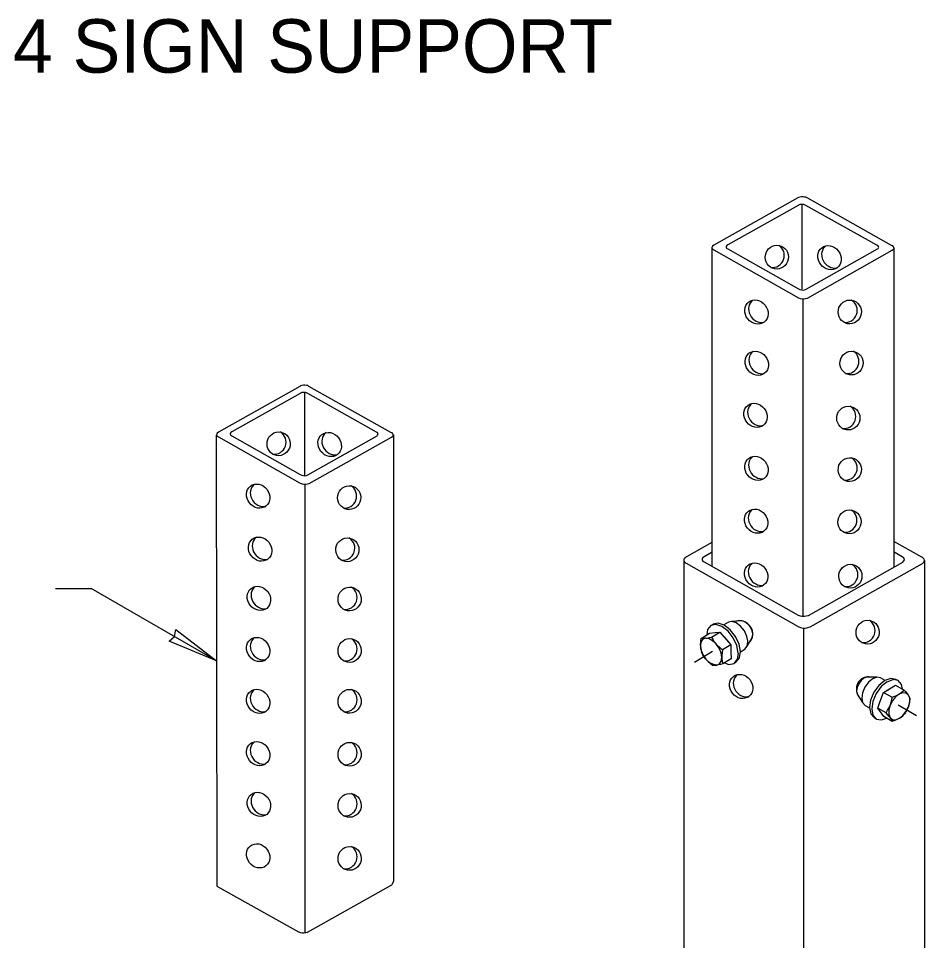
# Model space of a CAD drawing. Extents: x 99862 to 103680, y 99470 to 102076.
# Drawn here: x 101983.5 to 102390.3, y 100461.4 to 100875.6 of the extents above; entities that cross this region are included whole.
import ezdxf

# ---------------------------------------------------------------- set-up
doc = ezdxf.new("R2010")
doc.units = 0
for name, color, linetype in [('Level 15', 7, 'Continuous'), ('Level 20', 7, 'Continuous'), ('Level 3', 7, 'Continuous'), ('Level 5', 7, 'Continuous'), ('Level 9', 7, 'Continuous')]:
    doc.layers.add(name, color=color, linetype=linetype)

msp = doc.modelspace()

# ---------------------------------------------------------------- linework, layer by layer
at = {"layer": 'Level 15'}
for p, q in [((102000.1, 100619.57), (102016.1, 100619.57)), ((102072.39, 100587.07), (102016.1, 100619.57)), ((102286.95, 100586.46), (102295.04, 100591.39)), ((102386.64, 100562.41), (102378.4, 100567.09))]:
    msp.add_line(p, q, dxfattribs=at)
msp.add_lwpolyline([(102072.39, 100587.07), (102051.13, 100595.9), (102053.53, 100597.96), (102054.11, 100601.07)], close=True, dxfattribs=at)
at = {"layer": 'Level 3'}
for p, q in [((102335.18, 100792.03), (102335.18, 100754.01)), ((102335.82, 100607.07), (102335.82, 100749.87)), ((102112.05, 100670.24), (102112.05, 100707.51)), ((102072.26, 100688.3), (102072.51, 100485.85)), ((102151.85, 100688.51), (102151.85, 100488.15)), ((102112.05, 100666.45), (102112.05, 100465.01)), ((102292.9, 100601.14), (102292.51, 100598.72)), ((102336.03, 100354.46), (102336.03, 100601.71)), ((102304.75, 100585.94), (102306.21, 100587.74)), ((102306.67, 100590.55), (102306.21, 100587.74)), ((102373.51, 100577.68), (102376.19, 100578.64)), ((102378.46, 100578.23), (102376.19, 100578.64)), ((102370.91, 100560.5), (102373.21, 100561.33)), ((102151.85, 100488.15), (102151.16, 100486.47)), ((102072.51, 100485.85), (102109.31, 100465.35))]:
    msp.add_line(p, q, dxfattribs=at)
for points in [[(102376.5, 100772.58), (102376.44, 100772.7), (102376.36, 100773.02), (102376.08, 100773.43), (102375.51, 100773.57), (102337.6, 100794.94), (102337.03, 100795.36), (102336.46, 100795.36), (102335.75, 100795.5), (102335.04, 100795.5), (102334.33, 100795.36), (102333.76, 100795.22), (102333.34, 100794.94), (102295.71, 100773.71), (102295.14, 100773.3), (102294.87, 100772.78), (102294.84, 100772.71)], [(102333.62, 100754.15), (102334.33, 100753.87), (102335.04, 100753.73), (102335.75, 100753.59), (102336.46, 100753.73), (102337.17, 100754.01), (102369.12, 100772.05), (102369.4, 100772.32), (102369.69, 100772.88), (102369.55, 100773.16), (102369.26, 100773.57), (102368.84, 100773.71), (102337.03, 100791.61), (102336.46, 100791.89), (102336.03, 100792.03), (102335.47, 100792.03), (102334.9, 100792.03), (102334.33, 100792.03), (102333.76, 100791.75), (102333.48, 100791.61), (102301.96, 100773.85), (102301.53, 100773.57), (102301.25, 100773.16), (102301.25, 100772.88), (102301.39, 100772.46), (102301.53, 100772.32), (102301.96, 100772.05), (102333.62, 100754.15)], [(102294.86, 100772.74), (102294.86, 100640.13)], [(102294.86, 100772.46), (102295, 100772.19), (102295.28, 100771.91), (102295.71, 100771.63), (102333.62, 100750.12), (102334.47, 100749.85), (102335.32, 100749.71), (102336.03, 100749.71), (102336.89, 100749.85), (102337.74, 100749.99), (102375.79, 100771.49), (102376.36, 100771.91), (102376.43, 100772.19)], [(102376.5, 100772.58), (102376.5, 100640.71)], [(102151.67, 100688.53), (102151.53, 100689.07), (102151.25, 100689.47), (102150.7, 100689.61), (102113.91, 100710.34), (102113.36, 100710.75), (102112.81, 100710.75), (102112.12, 100710.88), (102111.43, 100710.88), (102110.75, 100710.75), (102110.19, 100710.61), (102109.78, 100710.34), (102073.27, 100689.74), (102072.72, 100689.34), (102072.58, 100688.94), (102072.26, 100688.3)], [(102110.06, 100670.76), (102110.75, 100670.49), (102111.43, 100670.36), (102112.12, 100670.22), (102112.81, 100670.36), (102113.5, 100670.63), (102144.5, 100688.13), (102144.78, 100688.4), (102145.05, 100688.94), (102144.91, 100689.2), (102144.64, 100689.61), (102144.23, 100689.74), (102113.36, 100707.11), (102112.81, 100707.38), (102112.4, 100707.51), (102111.85, 100707.51), (102111.3, 100707.51), (102110.75, 100707.51), (102110.19, 100707.24), (102109.92, 100707.11), (102079.33, 100689.88), (102078.92, 100689.61), (102078.64, 100689.2), (102078.64, 100688.94), (102078.78, 100688.53), (102078.92, 100688.4), (102079.33, 100688.13), (102110.06, 100670.76)], [(102072.58, 100688.26), (102072.86, 100687.99), (102073.27, 100687.72), (102110.06, 100666.86)], [(102110.06, 100666.86), (102110.88, 100666.59), (102111.71, 100666.45), (102112.4, 100666.45), (102113.23, 100666.59), (102114.05, 100666.72), (102150.98, 100687.59), (102151.53, 100687.99), (102151.6, 100688.26)], [(102376.5, 100640.71), (102376.5, 100629)], [(102390.27, 100632.16), (102390.28, 100632.19), (102390.13, 100632.74), (102389.57, 100633.3), (102389, 100633.58), (102376.5, 100640.65)], [(102294.86, 100640.24), (102283.35, 100633.71), (102282.64, 100633.16), (102282.22, 100632.74), (102282.22, 100632.3)], [(102294.86, 100640.13), (102294.86, 100629.41)], [(102282.22, 100632.52), (102282.22, 100384.98), (102282.33, 100384.6)], [(102295, 100635.93), (102291.31, 100633.85), (102290.74, 100633.44), (102290.45, 100633.02), (102290.45, 100632.47), (102290.6, 100632.05), (102290.88, 100631.77), (102291.31, 100631.49), (102333.48, 100607.63), (102334.47, 100607.21), (102335.32, 100607.07), (102336.32, 100607.07), (102337.17, 100607.21), (102338.16, 100607.49), (102380.48, 100631.36), (102381.05, 100631.91), (102381.33, 100632.47), (102381.19, 100633.02), (102380.76, 100633.44), (102380.2, 100633.71), (102376.65, 100635.8)], [(102282.22, 100632.3), (102282.22, 100632.19), (102282.36, 100631.63), (102282.79, 100631.22), (102283.21, 100630.94), (102333.48, 100602.5), (102334.61, 100602.08), (102335.61, 100601.8), (102336.74, 100601.8), (102337.88, 100602.08), (102338.87, 100602.36), (102389.42, 100630.8), (102389.99, 100631.36), (102390.27, 100632.16)], [(102390.28, 100632.16), (102390.28, 100385.26), (102390.24, 100385.2)], [(102296.63, 100603.43), (102294.37, 100602.93), (102294.37, 100602.93)], [(102299.33, 100602.56), (102296.63, 100603.43), (102296.63, 100603.43)], [(102294.37, 100602.93), (102292.9, 100601.14), (102292.9, 100601.14)], [(102302.07, 100600.46), (102299.33, 100602.56), (102299.33, 100602.56)], [(102304.43, 100597.43), (102302.07, 100600.46), (102302.07, 100600.46)], [(102306.04, 100593.95), (102304.43, 100597.43), (102304.43, 100597.43)], [(102306.67, 100590.55), (102306.67, 100590.55), (102306.04, 100593.95), (102306.04, 100593.95)], [(102300.4, 100586.12), (102302.49, 100585.44), (102302.49, 100585.44)], [(102302.49, 100585.44), (102304.75, 100585.94), (102304.75, 100585.94)], [(102370.83, 100575.48), (102368.57, 100572.38), (102368.57, 100572.38)], [(102373.51, 100577.68), (102373.51, 100577.68), (102370.83, 100575.48), (102370.83, 100575.48)], [(102379.99, 100576.49), (102378.46, 100578.23), (102378.46, 100578.23)], [(102380.42, 100574.34), (102379.99, 100576.49), (102379.99, 100576.49)], [(102368.57, 100572.38), (102367.07, 100568.85), (102367.07, 100568.85)], [(102367.07, 100568.85), (102366.55, 100565.44), (102366.55, 100565.44)], [(102366.55, 100565.44), (102367.1, 100562.65), (102367.1, 100562.65)], [(102367.1, 100562.65), (102368.63, 100560.92), (102368.63, 100560.92)], [(102368.63, 100560.92), (102370.91, 100560.5), (102370.91, 100560.5)], [(102109.31, 100465.35), (102110.14, 100465.08), (102110.96, 100464.95), (102111.65, 100464.95), (102112.48, 100465.08), (102113.31, 100465.22), (102151.16, 100486.47)]]:
    msp.add_lwpolyline(points, dxfattribs=at)
for centre, major_axis, ratio in [((102323.97, 100768.38), (-0.95, -5.27), 0.972281), ((102347.62, 100768.13), (-3.5, 4.49), 0.875232), ((102314.82, 100743.71), (-3.5, 4.49), 0.875232), ((102356.7, 100743.76), (-0.95, -5.27), 0.972281), ((102314.97, 100720.68), (-3.5, 4.49), 0.875232), ((102357.48, 100720.79), (-0.95, -5.27), 0.972281), ((102314.4, 100697.3), (-3.5, 4.49), 0.875232), ((102356.06, 100696.09), (-0.95, -5.27), 0.972281), ((102100.32, 100684.56), (-0.95, -5.27), 0.972281), ((102123.24, 100684.21), (-3.5, 4.49), 0.875232), ((102314.82, 100673.5), (-3.5, 4.49), 0.875232), ((102356.7, 100672.92), (-0.95, -5.27), 0.972281), ((102091.14, 100661.04), (-3.5, 4.49), 0.875232), ((102131.98, 100660.36), (-0.95, -5.27), 0.972281), ((102314.68, 100649.77), (-3.5, 4.49), 0.875232), ((102356.56, 100649.48), (-0.95, -5.27), 0.972281), ((102092, 100637.24), (-3.5, 4.49), 0.875232), ((102131.17, 100636.95), (-0.95, -5.27), 0.972281), ((102314.68, 100625.63), (-3.5, 4.49), 0.875232), ((102356.98, 100625.06), (-0.95, -5.27), 0.972281), ((102091.48, 100615.12), (-3.5, 4.49), 0.875232), ((102132.19, 100614.83), (-0.95, -5.27), 0.972281), ((102364.72, 100599.94), (-0.95, -5.27), 0.972281), ((102091.14, 100592.16), (-3.5, 4.49), 0.875232), ((102132.19, 100591.7), (-0.95, -5.27), 0.972281), ((102307.96, 100575.56), (-3.5, 4.49), 0.875232), ((102091.14, 100568.86), (-3.5, 4.49), 0.875232), ((102132.19, 100568.91), (-0.95, -5.27), 0.972281), ((102091.14, 100545.39), (-3.5, 4.49), 0.875232), ((102132.19, 100545.11), (-0.95, -5.27), 0.972281), ((102091.48, 100522.6), (-3.5, 4.49), 0.875232), ((102132.19, 100522.14), (-0.95, -5.27), 0.972281), ((102091.14, 100499.47), (-3.5, 4.49), 0.875232), ((102132.19, 100498.34), (-0.95, -5.27), 0.972281)]:
    msp.add_ellipse(centre, major_axis=major_axis, ratio=ratio, dxfattribs=at)
for centre, major_axis, ratio, start_param, end_param in [((102322.12, 100769.06), (-0.95, -5.27), 0.972281, 0.021287, 2.783374), ((102349.35, 100768.87), (-3.5, 4.49), 0.875232, 6.248227, 9.013354), ((102316.55, 100744.45), (-3.5, 4.49), 0.875232, 6.248227, 9.013354), ((102354.85, 100744.43), (-0.95, -5.27), 0.972281, 0.021287, 2.783374), ((102316.69, 100721.42), (-3.5, 4.49), 0.875232, 6.248227, 9.013354), ((102355.63, 100721.47), (-0.95, -5.27), 0.972281, 0.021287, 2.783374), ((102316.12, 100698.04), (-3.5, 4.49), 0.875232, 6.248227, 9.013354), ((102354.21, 100696.77), (-0.95, -5.27), 0.972281, 0.021287, 2.783374), ((102098.48, 100685.24), (-0.95, -5.27), 0.972281, 0.021287, 2.783374), ((102124.97, 100684.96), (-3.5, 4.49), 0.875232, 6.248227, 9.013354), ((102316.55, 100674.25), (-3.5, 4.49), 0.875232, 6.248227, 9.013354), ((102354.85, 100673.6), (-0.95, -5.27), 0.972281, 0.021287, 2.783374), ((102092.87, 100661.79), (-3.5, 4.49), 0.875232, 6.248227, 9.013354), ((102130.13, 100661.04), (-0.95, -5.27), 0.972281, 0.021287, 2.783374), ((102316.41, 100650.52), (-3.5, 4.49), 0.875232, 6.248227, 9.013354), ((102354.71, 100650.15), (-0.95, -5.27), 0.972281, 0.021287, 2.783374), ((102093.72, 100637.99), (-3.5, 4.49), 0.875232, 6.248227, 9.013354), ((102129.32, 100637.63), (-0.95, -5.27), 0.972281, 0.021287, 2.783374), ((102316.41, 100626.38), (-3.5, 4.49), 0.875232, 6.248227, 9.013354), ((102355.14, 100625.73), (-0.95, -5.27), 0.972281, 0.021287, 2.783374), ((102093.21, 100615.86), (-3.5, 4.49), 0.875232, 6.248227, 9.013354), ((102130.35, 100615.51), (-0.95, -5.27), 0.972281, 0.021287, 2.783374), ((102307.96, 100599.7), (-3.5, 4.49), 0.875232, 3.212624, 6.015506), ((102309.69, 100600.44), (-3.5, 4.49), 0.875232, 6.248227, 6.306195), ((102362.88, 100600.62), (-0.95, -5.27), 0.972281, 0.021287, 2.783374), ((102092.87, 100592.9), (-3.5, 4.49), 0.875232, 6.248227, 9.013354), ((102130.35, 100592.38), (-0.95, -5.27), 0.972281, 0.021287, 2.783374), ((102309.69, 100576.3), (-3.5, 4.49), 0.875232, 6.248227, 9.013354), ((102364.86, 100574.52), (-0.95, -5.27), 0.972281, 3.09812, 5.25118), ((102092.87, 100569.6), (-3.5, 4.49), 0.875232, 6.248227, 9.013354), ((102130.35, 100569.58), (-0.95, -5.27), 0.972281, 0.021287, 2.783374), ((102092.87, 100546.14), (-3.5, 4.49), 0.875232, 6.248227, 9.013354), ((102130.35, 100545.78), (-0.95, -5.27), 0.972281, 0.021287, 2.783374), ((102093.21, 100523.34), (-3.5, 4.49), 0.875232, 6.248227, 9.013354), ((102130.35, 100522.82), (-0.95, -5.27), 0.972281, 0.021287, 2.783374), ((102130.35, 100499.02), (-0.95, -5.27), 0.972281, 0.021287, 2.783374)]:
    msp.add_ellipse(centre, major_axis=major_axis, ratio=ratio, start_param=start_param, end_param=end_param, dxfattribs=at)
at = {"layer": 'Level 5'}
for p, q in [((102294.37, 100602.93), (102295.4, 100603.48)), ((102368.63, 100560.92), (102367.66, 100561.56))]:
    msp.add_line(p, q, dxfattribs=at)
for points in [[(102304.9, 100586.13), (102305.75, 100586.65), (102307.22, 100588.44), (102307.67, 100591.23), (102307.04, 100594.61), (102305.43, 100598.05), (102303.08, 100601.04), (102300.35, 100603.13), (102297.65, 100603.98), (102295.4, 100603.48)], [(102307.65, 100591.09), (102309.63, 100592.31), (102310.68, 100593.59), (102311.01, 100595.6), (102310.98, 100596.09), (102310.56, 100598.02), (102309.4, 100600.49), (102307.71, 100602.64), (102305.75, 100604.14), (102303.82, 100604.75), (102302.2, 100604.39), (102300.22, 100603.17)], [(102310.68, 100593.59), (102310.68, 100593.59), (102312.94, 100597.54), (102313.15, 100598.88), (102313.13, 100599.21), (102312.85, 100600.49), (102312.08, 100602.14), (102310.96, 100603.58), (102309.65, 100604.57), (102308.36, 100604.98), (102308.36, 100604.98), (102303.82, 100604.75)], [(102368.9, 100579.71), (102368.9, 100579.71), (102364.35, 100579.77), (102363.08, 100579.31), (102362.8, 100579.14), (102361.81, 100578.27), (102360.74, 100576.79), (102360.03, 100575.12), (102359.79, 100573.49), (102360.06, 100572.16), (102360.06, 100572.16), (102362.46, 100568.3)], [(102372.56, 100578.27), (102370.53, 100579.41), (102368.9, 100579.71), (102366.99, 100579.03), (102366.57, 100578.76), (102365.08, 100577.46), (102363.48, 100575.25), (102362.42, 100572.73), (102362.06, 100570.29), (102362.46, 100568.3), (102363.56, 100567.06), (102365.59, 100565.92)], [(102378.23, 100578.27), (102377.36, 100578.76), (102375.09, 100579.18), (102372.42, 100578.22), (102369.77, 100576.04), (102367.54, 100572.96), (102366.06, 100569.45), (102365.56, 100566.06), (102366.12, 100563.28), (102367.66, 100561.56)]]:
    msp.add_lwpolyline(points, dxfattribs=at)
at = {"layer": 'Level 9'}
for p, q in [((102294.69, 100597.72), (102298.4, 100600)), ((102294.69, 100597.72), (102298.4, 100600)), ((102373.03, 100563.72), (102369.24, 100565.86)), ((102373.03, 100563.72), (102369.24, 100565.86))]:
    msp.add_line(p, q, dxfattribs=at)
for points in [[(102289.66, 100593.92), (102289.66, 100593.99), (102289.81, 100595.94), (102289.83, 100596.19), (102289.99, 100597.17), (102293.7, 100599.45), (102296.34, 100599.76)], [(102289.66, 100593.92), (102289.66, 100593.99), (102289.81, 100595.94), (102289.83, 100596.19), (102289.99, 100597.17), (102293.7, 100599.45), (102296.34, 100599.76)], [(102296.34, 100599.76), (102298.4, 100600), (102300.19, 100597.89)], [(102296.58, 100599.79), (102298.4, 100600), (102300.19, 100597.89)], [(102291.83, 100597.18), (102290.67, 100596.65), (102289.91, 100595.51), (102289.66, 100593.92)], [(102291.83, 100597.18), (102290.67, 100596.65), (102289.91, 100595.51), (102289.66, 100593.92)], [(102292.03, 100597.2), (102291.83, 100597.18), (102291.56, 100597.15), (102290.61, 100597.14), (102290.37, 100597.13), (102289.99, 100597.17)], [(102292.03, 100597.2), (102291.83, 100597.18), (102291.56, 100597.15), (102290.61, 100597.14), (102290.37, 100597.13), (102289.99, 100597.17)], [(102295.9, 100595.66), (102296.66, 100594.67), (102295.14, 100596.09), (102293.52, 100596.98), (102292.03, 100597.2), (102292.56, 100597.28), (102293.73, 100597.52), (102294.69, 100597.72), (102295.37, 100596.56), (102295.9, 100595.66)], [(102295.9, 100595.66), (102296.66, 100594.67), (102295.14, 100596.09), (102293.52, 100596.98), (102292.03, 100597.2), (102292.56, 100597.28), (102293.73, 100597.52), (102294.69, 100597.72), (102295.37, 100596.56), (102295.9, 100595.66)], [(102300.19, 100597.89), (102303.27, 100594.27), (102303.36, 100591.15)], [(102300.28, 100597.79), (102303.27, 100594.27), (102303.35, 100591.38)], [(102289.66, 100593.92), (102289.67, 100593.63), (102289.75, 100592.7), (102289.95, 100591.84), (102290.17, 100590.89)], [(102289.66, 100593.92), (102289.67, 100593.63), (102289.75, 100592.7), (102289.95, 100591.84), (102290.17, 100590.89)], [(102289.67, 100593.63), (102290.02, 100591.7), (102290.87, 100589.69), (102292.1, 100587.87)], [(102289.67, 100593.63), (102290.02, 100591.7), (102290.87, 100589.69), (102292.1, 100587.87)], [(102303.27, 100594.27), (102299.56, 100591.99), (102298.71, 100592.66), (102298.47, 100592.89), (102296.88, 100594.41), (102296.77, 100594.54), (102296.66, 100594.67)], [(102303.27, 100594.27), (102299.56, 100591.99), (102298.71, 100592.66), (102298.47, 100592.89), (102296.88, 100594.41), (102296.77, 100594.54), (102296.66, 100594.67)], [(102296.98, 100585.18), (102298.18, 100585.68), (102298.99, 100586.86), (102299.24, 100588.56), (102298.91, 100590.59), (102298.03, 100592.69), (102296.77, 100594.54)], [(102296.98, 100585.18), (102298.18, 100585.68), (102298.99, 100586.86), (102299.24, 100588.56), (102298.91, 100590.59), (102298.03, 100592.69), (102296.77, 100594.54)], [(102303.36, 100591.15), (102303.45, 100587.99), (102299.74, 100585.71), (102298.66, 100585.49), (102297.61, 100585.27), (102296.98, 100585.18)], [(102303.36, 100591.15), (102303.45, 100587.99), (102299.74, 100585.71), (102298.66, 100585.49), (102297.61, 100585.27), (102296.98, 100585.18)], [(102299.56, 100591.99), (102299.39, 100590.71), (102299.27, 100589.79), (102299.25, 100588.57), (102299.25, 100588.38), (102299.5, 100586.67), (102299.53, 100586.46), (102299.74, 100585.71)], [(102299.56, 100591.99), (102299.39, 100590.71), (102299.27, 100589.79), (102299.25, 100588.57), (102299.25, 100588.38), (102299.5, 100586.67), (102299.53, 100586.46), (102299.74, 100585.71)], [(102292.28, 100587.67), (102292.1, 100587.87), (102292.02, 100587.97), (102290.82, 100589.73), (102290.65, 100589.99), (102290.17, 100590.89)], [(102292.28, 100587.67), (102292.1, 100587.87), (102292.02, 100587.97), (102290.82, 100589.73), (102290.65, 100589.99), (102290.17, 100590.89)], [(102292.28, 100587.67), (102293.11, 100586.78), (102294.04, 100586.01), (102295.04, 100585.16), (102295.42, 100585.12), (102295.7, 100585.11), (102295.72, 100585.11), (102296.98, 100585.18)], [(102296.98, 100585.18), (102295.47, 100585.37), (102293.82, 100586.24), (102292.28, 100587.67)], [(102292.28, 100587.67), (102293.11, 100586.78), (102294.04, 100586.01), (102295.04, 100585.16), (102295.42, 100585.12), (102295.7, 100585.11), (102295.72, 100585.11), (102296.98, 100585.18)], [(102296.98, 100585.18), (102295.47, 100585.37), (102293.82, 100586.24), (102292.28, 100587.67)], [(102370.22, 100568.46), (102371.89, 100572.9), (102374.58, 100574.49)], [(102370.27, 100568.58), (102371.89, 100572.9), (102374.38, 100574.37)], [(102374.58, 100574.49), (102377.3, 100576.1), (102381.09, 100573.96), (102381.81, 100573.12), (102382.51, 100572.31), (102382.9, 100571.8)], [(102374.58, 100574.49), (102377.3, 100576.1), (102381.09, 100573.96), (102381.81, 100573.12), (102382.51, 100572.31), (102382.9, 100571.8)], [(102371.89, 100572.9), (102375.68, 100570.76), (102375.51, 100569.69), (102375.43, 100569.37), (102374.87, 100567.25), (102374.81, 100567.08), (102374.75, 100566.92)], [(102371.89, 100572.9), (102375.68, 100570.76), (102375.51, 100569.69), (102375.43, 100569.37), (102374.87, 100567.25), (102374.81, 100567.08), (102374.75, 100566.92)], [(102382.9, 100571.8), (102381.87, 100572.61), (102380.45, 100572.75), (102378.84, 100572.14), (102377.23, 100570.87), (102375.82, 100569.08), (102374.81, 100567.08)], [(102382.9, 100571.8), (102381.87, 100572.61), (102380.45, 100572.75), (102378.84, 100572.14), (102377.23, 100570.87), (102375.82, 100569.08), (102374.81, 100567.08)], [(102375.68, 100570.76), (102376.89, 100571.23), (102377.76, 100571.57), (102378.83, 100572.15), (102379, 100572.23), (102380.37, 100573.28), (102380.54, 100573.41), (102381.09, 100573.96)], [(102375.68, 100570.76), (102376.89, 100571.23), (102377.76, 100571.57), (102378.83, 100572.15), (102379, 100572.23), (102380.37, 100573.28), (102380.54, 100573.41), (102381.09, 100573.96)], [(102383, 100566.48), (102383.37, 100567.64), (102383.6, 100568.83), (102383.85, 100570.12), (102383.7, 100570.47), (102383.58, 100570.71), (102383.57, 100570.73), (102382.9, 100571.8)], [(102382.9, 100571.8), (102383.46, 100570.4), (102383.5, 100568.53), (102383, 100566.48)], [(102383, 100566.48), (102383.37, 100567.64), (102383.6, 100568.83), (102383.85, 100570.12), (102383.7, 100570.47), (102383.58, 100570.71), (102383.57, 100570.73), (102382.9, 100571.8)], [(102382.9, 100571.8), (102383.46, 100570.4), (102383.5, 100568.53), (102383, 100566.48)], [(102370.31, 100564.37), (102369.24, 100565.86), (102370.22, 100568.46)], [(102370.45, 100564.18), (102369.24, 100565.86), (102370.22, 100568.46)], [(102374.25, 100565.78), (102374.75, 100566.92), (102374.24, 100564.91), (102374.25, 100563.06), (102374.78, 100561.64), (102374.45, 100562.07), (102373.67, 100562.98), (102373.03, 100563.72), (102373.72, 100564.88), (102374.25, 100565.78)], [(102374.25, 100565.78), (102374.75, 100566.92), (102374.24, 100564.91), (102374.25, 100563.06), (102374.78, 100561.64), (102374.45, 100562.07), (102373.67, 100562.98), (102373.03, 100563.72), (102373.72, 100564.88), (102374.25, 100565.78)], [(102379.05, 100561.31), (102380.56, 100562.55), (102381.91, 100564.27), (102382.9, 100566.23)], [(102379.05, 100561.31), (102380.56, 100562.55), (102381.91, 100564.27), (102382.9, 100566.23)], [(102383, 100566.48), (102382.9, 100566.23), (102382.86, 100566.11), (102381.9, 100564.21), (102381.76, 100563.93), (102381.2, 100563.08)], [(102383, 100566.48), (102382.9, 100566.23), (102382.86, 100566.11), (102381.9, 100564.21), (102381.76, 100563.93), (102381.2, 100563.08)], [(102378.79, 100561.16), (102378.73, 100561.13), (102376.96, 100560.31), (102376.73, 100560.21), (102375.79, 100559.88), (102372, 100562.02), (102370.45, 100564.18)], [(102378.79, 100561.16), (102378.73, 100561.13), (102376.96, 100560.31), (102376.73, 100560.21), (102375.79, 100559.88), (102372, 100562.02), (102370.45, 100564.18)], [(102378.79, 100561.16), (102379.05, 100561.31), (102379.83, 100561.84), (102380.48, 100562.42), (102381.2, 100563.08)], [(102378.79, 100561.16), (102379.05, 100561.31), (102379.83, 100561.84), (102380.48, 100562.42), (102381.2, 100563.08)], [(102374.78, 100561.64), (102374.9, 100561.48), (102375.05, 100561.26), (102375.52, 100560.43), (102375.64, 100560.23), (102375.79, 100559.88)], [(102374.78, 100561.64), (102374.9, 100561.48), (102375.05, 100561.26), (102375.52, 100560.43), (102375.64, 100560.23), (102375.79, 100559.88)], [(102374.9, 100561.48), (102375.92, 100560.72), (102377.28, 100560.61), (102378.79, 100561.16)], [(102374.9, 100561.48), (102375.92, 100560.72), (102377.28, 100560.61), (102378.79, 100561.16)]]:
    msp.add_lwpolyline(points, dxfattribs=at)

# ---------------------------------------------------------------- texts
at = {"layer": 'Level 20'}
msp.add_text('TYPE ST-4 SIGN SUPPORT', height=24, dxfattribs=at).set_placement((101836.64, 100851.21))

doc.saveas('drawing.dxf')
